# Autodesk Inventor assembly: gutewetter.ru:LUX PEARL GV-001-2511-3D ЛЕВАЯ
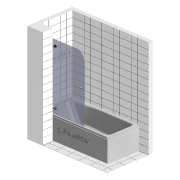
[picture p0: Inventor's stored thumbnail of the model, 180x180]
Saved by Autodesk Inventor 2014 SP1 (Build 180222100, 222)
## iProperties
Document SubType Name: Assembly
Designer: Чечуров
Mass: 24931.1 g
Surface Area: 373978 cm^2
Volume: 980587 cm^3
Density: 0.0254247 g/cm^3
Description: LUX PEARL GV-001-2511 ЛЕВАЯ
RuleStatus: InUse
Author: Чечуров
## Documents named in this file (22)
- P:\!  Продукция GuteWetter\LUX динамические модели и набор документов\PEARL\LUX PEARL GV-001-2511\LUX PEARL GV-001-2511 левая модель\LUX PEARL GV-001-2511 ЛЕВАЯ (модель).iam
- P:\!  Продукция GuteWetter\LUX динамические модели и набор документов\PEARL\LUX PEARL GV-001-2511\LUX PEARL GV-001-2511 левая модель\Вспомогательные файлы конструктора\Студия\Студия.ipt
- P:\!  Продукция GuteWetter\LUX динамические модели и набор документов\PEARL\LUX PEARL GV-001-2511\LUX PEARL GV-001-2511 левая модель\Вспомогательные файлы конструктора\Ручки\07.iam
- P:\!  Продукция GuteWetter\LUX динамические модели и набор документов\PEARL\LUX PEARL GV-001-2511\LUX PEARL GV-001-2511 левая модель\Вспомогательные файлы конструктора\Петли\CH25-0 L.iam
- P:\!  Продукция GuteWetter\LUX динамические модели и набор документов\PEARL\LUX PEARL GV-001-2511\LUX PEARL GV-001-2511 левая модель\Вспомогательные файлы конструктора\Ручки\113.iam
- P:\!  Продукция GuteWetter\LUX динамические модели и набор документов\PEARL\LUX PEARL GV-001-2511\LUX PEARL GV-001-2511 левая модель\Вспомогательные файлы конструктора\Ручки\Ручка CH12-40.ipt
- P:\!  Продукция GuteWetter\LUX динамические модели и набор документов\PEARL\LUX PEARL GV-001-2511\LUX PEARL GV-001-2511 левая модель\Вспомогательные файлы конструктора\Ручки\Ручка CH02.ipt
- P:\!  Продукция GuteWetter\LUX динамические модели и набор документов\PEARL\LUX PEARL GV-001-2511\LUX PEARL GV-001-2511 левая модель\Вспомогательные файлы конструктора\Ручки\Ручка CH01.ipt
- P:\!  Продукция GuteWetter\LUX динамические модели и набор документов\PEARL\LUX PEARL GV-001-2511\LUX PEARL GV-001-2511 левая модель\Вспомогательные файлы конструктора\Ручки\Ручка CH04.ipt
- P:\!  Продукция GuteWetter\LUX динамические модели и набор документов\PEARL\LUX PEARL GV-001-2511\LUX PEARL GV-001-2511 левая модель\Вспомогательные файлы конструктора\Трап\Трап 100х100 (2).ipt
- P:\!  Продукция GuteWetter\LUX динамические модели и набор документов\PEARL\LUX PEARL GV-001-2511\LUX PEARL GV-001-2511 левая модель\Вспомогательные файлы конструктора\Упаковка\Упаковка.ipt
- P:\!  Продукция GuteWetter\LUX динамические модели и набор документов\PEARL\LUX PEARL GV-001-2511\LUX PEARL GV-001-2511 левая модель\Вспомогательные файлы конструктора\Студия\Пол.ipt
- P:\!  Продукция GuteWetter\LUX динамические модели и набор документов\PEARL\LUX PEARL GV-001-2511\LUX PEARL GV-001-2511 левая модель\Вспомогательные файлы конструктора\Ручки\112.iam
- P:\!  Продукция GuteWetter\LUX динамические модели и набор документов\PEARL\LUX PEARL GV-001-2511\LUX PEARL GV-001-2511 левая модель\Вспомогательные файлы конструктора\Уплотнитель\UP600B6.01.ipt
- P:\!  Продукция GuteWetter\LUX динамические модели и набор документов\PEARL\LUX PEARL GV-001-2511\LUX PEARL GV-001-2511 левая модель\Вспомогательные файлы конструктора\Студия\Ванна\Ванна 170х80x50.iam
- P:\!  Продукция GuteWetter\LUX динамические модели и набор документов\PEARL\LUX PEARL GV-001-2511\LUX PEARL GV-001-2511 левая модель\Вспомогательные файлы конструктора\Студия\Стенка A.ipt
- P:\!  Продукция GuteWetter\LUX динамические модели и набор документов\PEARL\LUX PEARL GV-001-2511\LUX PEARL GV-001-2511 левая модель\Вспомогательные файлы конструктора\Крепеж\DUBEL 8x52.ipt
- P:\!  Продукция GuteWetter\LUX динамические модели и набор документов\PEARL\LUX PEARL GV-001-2511\LUX PEARL GV-001-2511 левая модель\Вспомогательные файлы конструктора\Крепеж\Саморез 6х55.ipt
- P:\!  Продукция GuteWetter\LUX динамические модели и набор документов\PEARL\LUX PEARL GV-001-2511\LUX PEARL GV-001-2511 левая модель\Вспомогательные файлы конструктора\Уплотнитель\UP606-13.ipt
- P:\!  Продукция GuteWetter\LUX динамические модели и набор документов\PEARL\LUX PEARL GV-001-2511\LUX PEARL GV-001-2511 левая модель\Вспомогательные файлы конструктора\Петли\CH25-11 L.iam
- P:\!  Продукция GuteWetter\LUX динамические модели и набор документов\PEARL\LUX PEARL GV-001-2511\LUX PEARL GV-001-2511 левая модель\Вспомогательные файлы конструктора\Стекло\Стекло.03 (2511) PEARL.ipt
- P:\!  Продукция GuteWetter\LUX динамические модели и набор документов\PEARL\LUX PEARL GV-001-2511\LUX PEARL GV-001-2511 левая модель\Вспомогательные файлы конструктора\Студия\LOGO GUTEWETTER.ipt
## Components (38 placed, 21 different names)
1. Студия:1 — Совмещение:514, Заподлицо:128, Заподлицо:129, Совмещение:609, Совмещение:614, Совмещение:669, Угол:1, Заподлицо:149
2. Трап 100х100 (2):1 — Заподлицо:130, Совмещение:515, Совмещение:516
3. Пол:1 — Совмещение:514, Заподлицо:128, Заподлицо:129, Заподлицо:130, Совмещение:515, Совмещение:516, Совмещение:610, Совмещение:633, Совмещение:670, Совмещение:674
4. Ванна 170х80x50:1 [sub-assembly] — Совмещение:609, Совмещение:610, Совмещение:614, Совмещение:662
5. Стенка A:1 — Совмещение:633, Совмещение:669, Совмещение:670, Совмещение:671, Совмещение:672, Совмещение:673
6. Стекло.03 (2511) PEARL:1 — Совмещение:307, Совмещение:308, Совмещение:309, Совмещение:428, Совмещение:429, Совмещение:430, Совмещение:431, Совмещение:432, Совмещение:433, Совмещение:486, Совмещение:487, Заподлицо:119, Совмещение:488, Совмещение:489, Совмещение:490, Совмещение:491, Совмещение:492, Совмещение:493, Совмещение:494, Заподлицо:120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
7. CH25-0 L:2 [sub-assembly] — Совмещение:428, Совмещение:429, Совмещение:430, Совмещение:663, Совмещение:665
8. CH25-0 L:3 [sub-assembly] — Совмещение:431, Совмещение:432, Совмещение:433, Совмещение:664, Совмещение:666
9. 07:1 [sub-assembly] — Совмещение:307, Совмещение:308, Совмещение:309
10. 113:1 [sub-assembly] — Совмещение:486, Совмещение:487, Заподлицо:119
11. 112:1 [sub-assembly] — Совмещение:526, Заподлицо:133, Совмещение:527
12. Ручка CH12-40:1 — Совмещение:496, Совмещение:497, Совмещение:498
13. Ручка CH01:1 — Совмещение:494, Заподлицо:120, Совмещение:495
14. Ручка CH02:1 — Совмещение:491, Совмещение:492, Совмещение:493
15. Ручка CH04:1 — Совмещение:488, Совмещение:489, Совмещение:490
16. Ручка CH12-40:2
17. Упаковка:1
18. UP600B6.01:1 — Совмещение:598, Заподлицо:139, Совмещение:608
19. UP606-13:1 — Совмещение:667, Заподлицо:148, Совмещение:668
20. CH25-11 L:1 [sub-assembly] — Совмещение:663, Совмещение:665, Совмещение:671, Совмещение:673
21. DUBEL 8x52:1
22. Саморез 6х55:1
23. DUBEL 8x52:2
24. Саморез 6х55:2
25. DUBEL 8x52:3
26. Саморез 6х55:3
27. DUBEL 8x52:4
28. Саморез 6х55:4
29. CH25-11 L:2 [sub-assembly] — Совмещение:664, Совмещение:666, Совмещение:672
30. DUBEL 8x52:5
31. Саморез 6х55:5
32. DUBEL 8x52:6
33. Саморез 6х55:6
34. DUBEL 8x52:7
35. Саморез 6х55:7
36. DUBEL 8x52:8
37. Саморез 6х55:8
38. LOGO GUTEWETTER:1 — Совмещение:674, Заподлицо:149
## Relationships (56: Mate 46, Flush 9, Angle 1)
- Совмещение:307 [Mate]: Стекло.03 (2511) PEARL:1 ↔ 07:1
- Совмещение:308 [Mate]: Стекло.03 (2511) PEARL:1 ↔ 07:1
- Совмещение:309 [Mate]: Стекло.03 (2511) PEARL:1 ↔ 07:1
- Совмещение:428 [Mate]: Стекло.03 (2511) PEARL:1 ↔ CH25-0 L:2
- Совмещение:429 [Mate]: Стекло.03 (2511) PEARL:1 ↔ CH25-0 L:2
- Совмещение:430 [Mate]: Стекло.03 (2511) PEARL:1 ↔ CH25-0 L:2
- Совмещение:431 [Mate]: Стекло.03 (2511) PEARL:1 ↔ CH25-0 L:3
- Совмещение:432 [Mate]: Стекло.03 (2511) PEARL:1 ↔ CH25-0 L:3
- Совмещение:433 [Mate]: Стекло.03 (2511) PEARL:1 ↔ CH25-0 L:3
- Совмещение:486 [Mate]: Стекло.03 (2511) PEARL:1 ↔ 113:1
- Совмещение:487 [Mate]: Стекло.03 (2511) PEARL:1 ↔ 113:1
- Заподлицо:119 [Flush]: Стекло.03 (2511) PEARL:1 ↔ 113:1
- Совмещение:488 [Mate]: Стекло.03 (2511) PEARL:1 ↔ Ручка CH04:1
- Совмещение:489 [Mate]: Стекло.03 (2511) PEARL:1 ↔ Ручка CH04:1
- Совмещение:490 [Mate]: Стекло.03 (2511) PEARL:1 ↔ Ручка CH04:1
- Совмещение:491 [Mate]: Стекло.03 (2511) PEARL:1 ↔ Ручка CH02:1
- Совмещение:492 [Mate]: Стекло.03 (2511) PEARL:1 ↔ Ручка CH02:1
- Совмещение:493 [Mate]: Стекло.03 (2511) PEARL:1 ↔ Ручка CH02:1
- Совмещение:494 [Mate]: Стекло.03 (2511) PEARL:1 ↔ Ручка CH01:1
- Заподлицо:120 [Flush]: Стекло.03 (2511) PEARL:1 ↔ Ручка CH01:1
- Совмещение:495 [Mate]: Стекло.03 (2511) PEARL:1 ↔ Ручка CH01:1
- Совмещение:496 [Mate]: Стекло.03 (2511) PEARL:1 ↔ Ручка CH12-40:1
- Совмещение:497 [Mate]: Стекло.03 (2511) PEARL:1 ↔ Ручка CH12-40:1
- Совмещение:498 [Mate]: Стекло.03 (2511) PEARL:1 ↔ Ручка CH12-40:1
- Совмещение:514 [Mate]: Студия:1 ↔ Пол:1
- Заподлицо:128 [Flush]: Студия:1 ↔ Пол:1
- Заподлицо:129 [Flush]: Студия:1 ↔ Пол:1
- Заподлицо:130 [Flush]: Трап 100х100 (2):1 ↔ Пол:1
- Совмещение:515 [Mate]: Трап 100х100 (2):1 ↔ Пол:1
- Совмещение:516 [Mate]: Трап 100х100 (2):1 ↔ Пол:1
- Совмещение:526 [Mate]: Стекло.03 (2511) PEARL:1 ↔ 112:1
- Заподлицо:133 [Flush]: Стекло.03 (2511) PEARL:1 ↔ 112:1
- Совмещение:527 [Mate]: Стекло.03 (2511) PEARL:1 ↔ 112:1
- Совмещение:598 [Mate]: Стекло.03 (2511) PEARL:1 ↔ UP600B6.01:1
- Заподлицо:139 [Flush]: Стекло.03 (2511) PEARL:1 ↔ UP600B6.01:1
- Совмещение:608 [Mate]: Стекло.03 (2511) PEARL:1 ↔ UP600B6.01:1
- Совмещение:609 [Mate]: Студия:1 ↔ Ванна 170х80x50:1
- Совмещение:610 [Mate]: Пол:1 ↔ Ванна 170х80x50:1
- Совмещение:614 [Mate]: Студия:1 ↔ Ванна 170х80x50:1
- Совмещение:633 [Mate]: Пол:1 ↔ Стенка A:1
- Совмещение:662 [Mate]: Ванна 170х80x50:1 ↔ Стекло.03 (2511) PEARL:1
- Совмещение:663 [Mate]: CH25-0 L:2 ↔ CH25-11 L:1
- Совмещение:664 [Mate]: CH25-0 L:3 ↔ CH25-11 L:2
- Совмещение:665 [Mate]: CH25-0 L:2 ↔ CH25-11 L:1
- Совмещение:666 [Mate]: CH25-0 L:3 ↔ CH25-11 L:2
- Совмещение:667 [Mate]: Стекло.03 (2511) PEARL:1 ↔ UP606-13:1
- Заподлицо:148 [Flush]: Стекло.03 (2511) PEARL:1 ↔ UP606-13:1
- Совмещение:668 [Mate]: Стекло.03 (2511) PEARL:1 ↔ UP606-13:1
- Совмещение:669 [Mate]: Студия:1 ↔ Стенка A:1
- Совмещение:670 [Mate]: Пол:1 ↔ Стенка A:1
- Совмещение:671 [Mate]: Стенка A:1 ↔ CH25-11 L:1
- Совмещение:672 [Mate]: Стенка A:1 ↔ CH25-11 L:2
- Совмещение:673 [Mate]: Стенка A:1 ↔ CH25-11 L:1
- Угол:1 [Angle]: Студия:1 ↔ Стекло.03 (2511) PEARL:1
- Совмещение:674 [Mate]: Пол:1 ↔ LOGO GUTEWETTER:1
- Заподлицо:149 [Flush]: Студия:1 ↔ LOGO GUTEWETTER:1
## Named parameters: d234_УГОЛ = 0, d242_УГОЛ = 0, d1041_d988_d719 = 0, d1042_d989_d720 = -7.5 mm, d1043_d990 = 0, d1044_d991 = 0, d1063_d1041_d988_d719 = 0, d1064_d1042_d989_d720 = -7.5 mm, d1065_d1063_d1041_d988_d719 = 0, d1066_d1064_d1042_d989_d720 = -7.5 mm, d1067_d1041_d988_d719 = 0, d1068_d1042_d989_d720 = -7.5 mm, d1115_d1041_d988_d719 = 0, d1116_d1042_d989_d720 = -7.5 mm, d1117_d1043_d990 = 0, d1118_d1044_d991 = 0, d1121_d1063_d1041_d988_d719 = 0, d1122_d1064_d1042_d989_d720 = -7.5 mm, d1123_d1065_d1063_d1041_d988_d719 = 0, d1124_d1066_d1064_d1042_d989_d720 = -7.5 mm, d1125_d1067_d1041_d988_d719 = 0, d1126_d1068_d1042_d989_d720 = -7.5 mm, d1127_d1069 = 0, d1128_d1070 = 0, d1129_d1071 = 0, d1130_d1072 = 0, d1131_d1073 = 0, d1132_d1074 = 0
